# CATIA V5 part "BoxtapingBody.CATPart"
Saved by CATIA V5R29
Part number: BoxtapingBody
Bounding box of the stored display mesh (mm): x -260 to 260, y -52.738 to 710, z -355.5 to 355.5
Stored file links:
  C:\Users\Administrator\Desktop\프로젝트\Boxfold\BoxtapingBody.CATPart
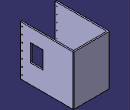
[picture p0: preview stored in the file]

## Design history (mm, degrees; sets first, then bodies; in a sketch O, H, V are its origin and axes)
Body1 (main body)
  DatumSurface1
  DatumSurface2
  Sketch1 on xy-plane, origin (0, 0, 0), H (-1, 0, 0), V (0, -1, 0)
    line L1 (-250, 52.7379) -> (-250, -700)
    line L2 (-250, -700) -> (250, -700)
    line L3 (250, -700) -> (250, 52.7379)
    length L2 = 500
    distance L2 H = 700
    vertical: L1 V, L3 V
    horizontal: L2 H
    symmetry: L3 L1 V
  Pad1: profile Sketch1, direction (0, 0, 1), up to face of DatumSurface1, opposite side up to face of DatumSurface2, thin wall 10, second thickness 10
  Fillet1: radius 10, on edge [face of Pad1 | face of Pad1] (x4)
  Sketch2 on face of Pad1, origin (260, -5.7247, 212.1343), H (0, 1, 0), V (0, 0, 1)
    point P1 (-22.0132, 93.3657)
    reference projected line E1 (-47.0132, 143.3657) -> (715.7247, 143.3657) from edge [face of Pad1 | start face of Pad1]
    reference projected line E2 (-47.0132, -567.6343) -> (-47.0132, 143.3657) from edge [face of Pad1 | face of Pad1]
    distance P1 E1 = 50
    distance P1 E2 = 25
  Hole1: placed by Sketch2, at (260, -27.7379, 305.5) direction (-1, 0, 0), diameter 8.6, through (limit type 6), counterbore diameter 14, counterbore depth 8.6
  RectPattern1: of Hole1, direction 1 instances 7, spacing 100, along edge [face of Pad1 | face of Pad1] reversed
  Sketch3 on face of Pad1, origin (-260, -26.3009, 321.6801), H (0, 1, 0), V (0, 0, -1)
    point P1 (-1.4369, 16.1801)
    reference projected circle E1 centre (-1.4369, 16.1801) radius 7 from edge [face of Pad1 | face of Hole1]
    concentricity: E1 P1
  Hole2: placed by Sketch3, at (-260, -27.7379, 305.5) direction (1, 0, 0), diameter 8.6, through (limit type 6), counterbore diameter 14, counterbore depth 8.6
  RectPattern2: of Hole2, direction 1 instances 7, spacing 100, along edge [face of Pad1 | face of Pad1] reversed
  DatumCurve1
  DatumSurface3
  DatumCurve2
  DatumCurve3
  Sketch4 on face of Pad1, origin (260, 0, 0), H (0, 1, 0), V (0, 0, 1)
    line L1 (94.0761, 166.15) -> (274.0761, 166.15)
    line L2 (274.0761, 166.15) -> (274.0761, -83.85)
    line L3 (274.0761, -83.85) -> (94.0761, -83.85)
    line L4 (94.0761, -83.85) -> (94.0761, 166.15)
    reference projected point E1 (194.0761, 41.15) from edge of DatumCurve1
    reference intersected line E2 through (294.0761, 0) direction (0, 1) from face of DatumSurface3
    reference projected point E4 (194.0761, 41.15) from edge of DatumCurve3
    distance L4 E1 = 100
    distance L2 E2 = 20
    distance L1 L3 = 250
    distance L1 E4 = 125
    horizontal: L1 H, L3 H
    vertical: L2 V, L4 V
  Pocket1: profile Sketch4, direction (-1, 0, 0), through (limit type 6)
